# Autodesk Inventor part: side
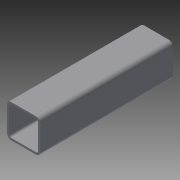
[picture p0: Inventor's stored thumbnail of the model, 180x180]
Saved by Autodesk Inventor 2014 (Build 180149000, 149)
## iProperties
Created: 2008-04
Part Number: side
Document SubType Name: Modeling
Designer: Jayson Martinez
Density: 1 g/cm^3
Material: Generic
Appearance: Default
Author: Jayson Martinez
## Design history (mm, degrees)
sketch "Sketch1"
  geometry: L1 (6.35, 0)-(44.45, 0); L2 (50.8, 6.35)-(50.8, 44.45); L3 (44.45, 50.8)-(6.35, 50.8); L4 (0, 44.45)-(0, 6.35); L5 (3.175, 6.35)-(3.175, 44.45); L6 (6.35, 47.625)-(44.45, 47.625); L7 (47.625, 44.45)-(47.625, 6.35); L8 (44.45, 3.175)-(6.35, 3.175); A1 r 6.35 centre (6.35, 44.45) between (6.35, 50.8) and (0, 44.45); A2 r 6.35 centre (6.35, 6.35) between (0, 6.35) and (6.35, 0); A3 r 6.35 centre (44.45, 6.35) between (44.45, 0) and (50.8, 6.35); A4 r 6.35 centre (44.45, 44.45) between (50.8, 44.45) and (44.45, 50.8); A5 r 3.175 centre (6.35, 44.45) between (6.35, 47.625) and (3.175, 44.45); A6 r 3.175 centre (44.45, 44.45) between (47.625, 44.45) and (44.45, 47.625); A7 r 3.175 centre (44.45, 6.35) between (44.45, 3.175) and (47.625, 6.35); A8 r 3.175 centre (6.35, 6.35) between (3.175, 6.35) and (6.35, 3.175); 3 further points
  constraints: 16 end point, 16 point on circle, 8 centre point, 8 tangent, 6 point on line, 4 parallel, 3 equal radius, 2 perpendicular, 1 horizontal, 7 other
  dimensions: "d0" = 50.8 distance of point (0, 0) point (50.8, 0) (= MemberWidth); "d1" = 50.8 distance of point (0, 50.8) point (0, 0) (= MemberWidth); "d2" = 6.35 radius of A1 (= 2 x MemberThickness); "d3" = 3.175 distance between parallel lines of L4 L5 (= MemberThickness)
extrude "Extrusion1" new body sketch "Sketch1" distance "d4" = 203.2 (= SideLength); taper "d5" = 0 deg
workplane "Work Plane1"
body "Solid1"
other parameters: "d6" = -25.4 (= -0.5 x MemberWidth), "MemberThickness" = 3.175, "MemberWidth" = 50.8, "SideLength" = 203.2
